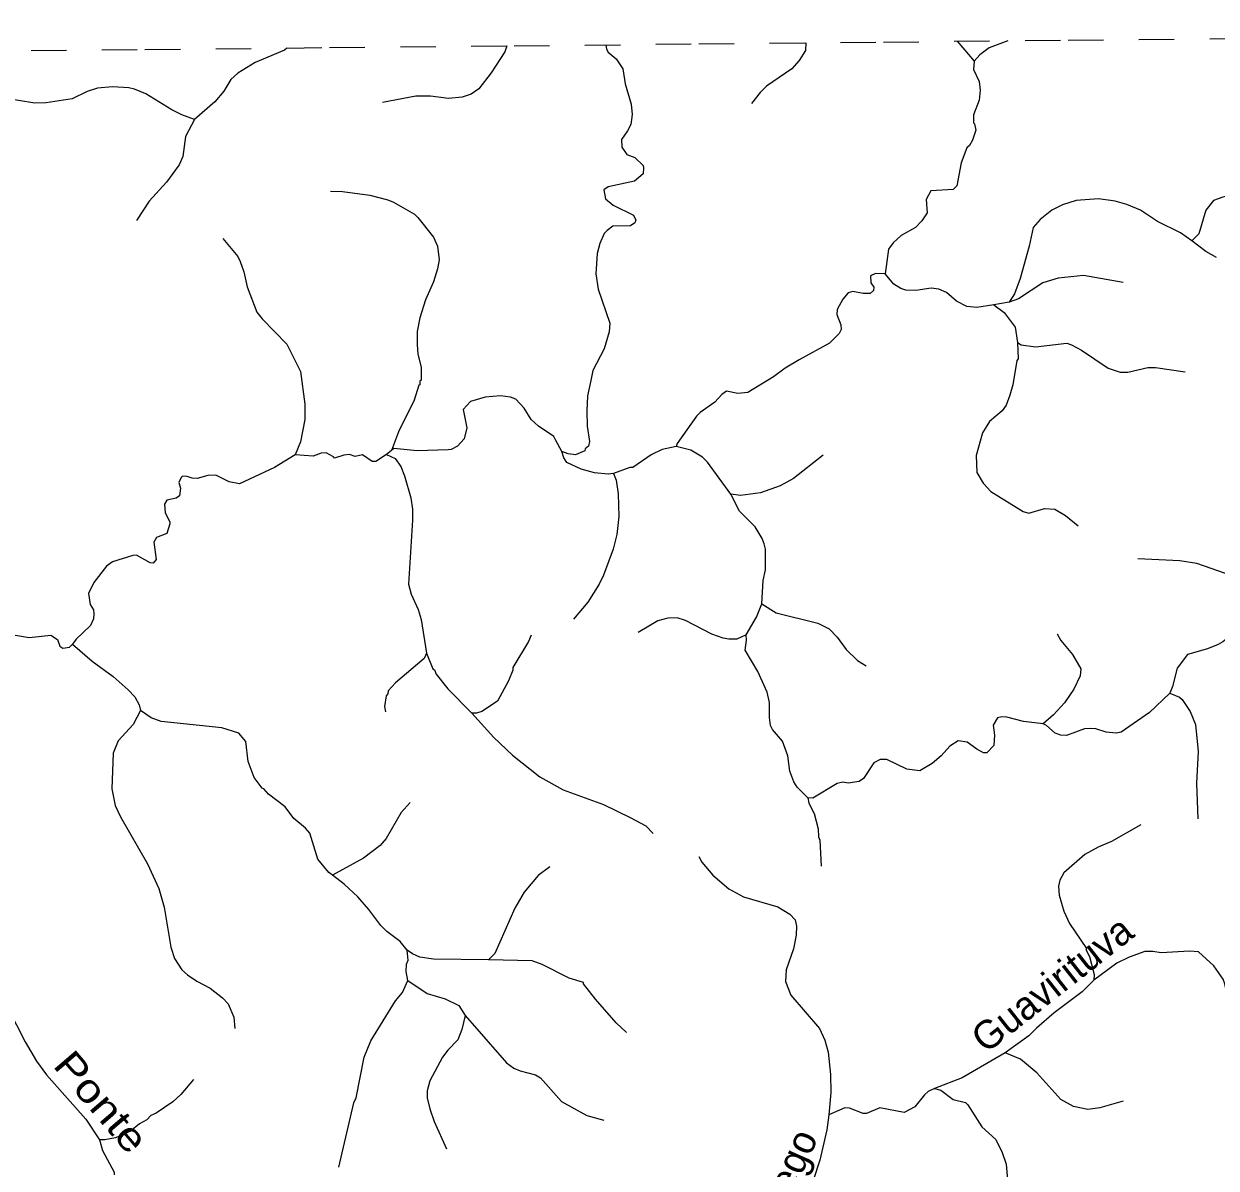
# Model space of a CAD drawing. Extents: x 346.5 to 372.4, y 7400.3 to 7428.2.
# Drawn here: x 348.817 to 352.188, y 7424.867 to 7428.102 of the extents above; entities that cross this region are included whole.
import ezdxf
from ezdxf.enums import TextEntityAlignment as Align

# ---------------------------------------------------------------- set-up
doc = ezdxf.new("R2010")
doc.units = 0
doc.header["$LTSCALE"] = 0.032
doc.linetypes.add('SHORT_DASHED', pattern=[2.7, 1.5, -1.2])
doc.layers.add('53', color=7, linetype='SHORT_DASHED', lineweight=13)
doc.layers.add('7', color=7, linetype='Continuous', lineweight=25)
doc.layers.add('61', color=7, linetype='Continuous')

msp = doc.modelspace()

# ---------------------------------------------------------------- linework, layer by layer
at = {"layer": '53'}
msp.add_lwpolyline([(346.5495, 7428.0029), (347.0715, 7428.0083), (347.5936, 7428.0137), (348.1156, 7428.019), (348.6376, 7428.0243), (349.1596, 7428.0297), (349.6816, 7428.035), (350.2036, 7428.0402), (350.7257, 7428.0455), (351.2477, 7428.0507), (351.7697, 7428.0559), (352.2917, 7428.0611), (352.8137, 7428.0663), (353.3357, 7428.0715), (353.8577, 7428.0766), (354.3798, 7428.0818), (354.9018, 7428.0869), (355.4238, 7428.092), (355.9458, 7428.0971), (356.4678, 7428.1021)], dxfattribs=at)
at = {"layer": '7'}
msp.add_line((351.4558, 7428.0528), (351.5038, 7427.9967), dxfattribs=at)
for points in [[(351.5993, 7428.0542), (351.5466, 7428.0343), (351.5195, 7428.0144), (351.5038, 7427.9967)], [(349.5611, 7428.0338), (349.5543, 7428.0279), (349.4714, 7427.9929), (349.422, 7427.9626), (349.4028, 7427.9451), (349.3821, 7427.9116), (349.3574, 7427.8821), (349.2997, 7427.832)], [(350.1829, 7428.04), (350.1766, 7428.0232), (350.1384, 7427.9634), (350.1033, 7427.9187), (350.0818, 7427.9036), (350.0563, 7427.8948), (350.0181, 7427.8908), (349.9671, 7427.8972), (349.9256, 7427.8972), (349.8308, 7427.8797)], [(350.4626, 7428.0428), (350.4645, 7428.0309), (350.4693, 7428.0224), (350.4914, 7428.0032), (350.5106, 7427.9753), (350.5169, 7427.9323), (350.5337, 7427.8749), (350.5369, 7427.8462), (350.5329, 7427.8175), (350.5241, 7427.7992), (350.5066, 7427.7753), (350.5082, 7427.7538), (350.5217, 7427.7323), (350.5441, 7427.7243), (350.568, 7427.702), (350.5687, 7427.6948), (350.568, 7427.6781), (350.544, 7427.6573), (350.4691, 7427.6414), (350.4572, 7427.6327), (350.4612, 7427.6079), (350.4835, 7427.5896), (350.5409, 7427.5617), (350.5472, 7427.5474), (350.5448, 7427.5394), (350.5321, 7427.5314), (350.4827, 7427.5298), (350.466, 7427.5179), (350.458, 7427.5099), (350.4452, 7427.4812), (350.438, 7427.4525), (350.4341, 7427.3952), (350.4404, 7427.3521), (350.4739, 7427.2557), (350.4723, 7427.231), (350.458, 7427.1832), (350.4261, 7427.1226), (350.4197, 7427.0939), (350.411, 7427.0509), (350.4086, 7427.0078), (350.4102, 7426.9648), (350.4165, 7426.9218), (350.4133, 7426.9082), (350.4038, 7426.9003), (350.403, 7426.8955), (350.3767, 7426.8835), (350.3564, 7426.8861), (350.3379, 7426.8934)], [(351.0284, 7428.0485), (351.027, 7428.0271), (351.0087, 7427.9984), (350.9887, 7427.9745), (350.917, 7427.9259), (350.8987, 7427.9084), (350.8748, 7427.8773)], [(351.5038, 7427.9967), (351.502, 7427.9729), (351.5179, 7427.9395), (351.5211, 7427.9148), (351.5179, 7427.8861), (351.502, 7427.8446), (351.502, 7427.8223), (351.5052, 7427.8199), (351.5083, 7427.8016), (351.4988, 7427.7729), (351.4908, 7427.7578), (351.4836, 7427.7514), (351.4669, 7427.7092), (351.4549, 7427.6446), (351.4446, 7427.6334), (351.3816, 7427.6302), (351.3681, 7427.6056), (351.3713, 7427.5681), (351.3561, 7427.545), (351.3378, 7427.5266), (351.2972, 7427.5035), (351.2748, 7427.4828), (351.2613, 7427.4653), (351.2518, 7427.3956)], [(349.2997, 7427.832), (349.2642, 7427.8446), (349.2355, 7427.859), (349.1622, 7427.9044), (349.1303, 7427.9179), (349.1143, 7427.9211), (349.0681, 7427.9243), (349.0251, 7427.9203), (348.9964, 7427.9108), (348.9534, 7427.8901), (348.88, 7427.8789), (348.8482, 7427.8781), (348.7557, 7427.8932), (348.7246, 7427.8941)], [(349.2997, 7427.832), (349.2745, 7427.7841), (349.2665, 7427.7275), (349.2562, 7427.7036), (349.2203, 7427.655), (349.1717, 7427.6008), (349.1359, 7427.5458)], [(352.6313, 7427.6853), (352.5476, 7427.7068), (352.4838, 7427.7179), (352.4328, 7427.7203), (352.4009, 7427.7147), (352.3579, 7427.6892), (352.2862, 7427.6374), (352.2543, 7427.6231), (352.2065, 7427.6119), (352.1802, 7427.6023), (352.1587, 7427.5753), (352.1395, 7427.5083), (352.1192, 7427.489)], [(349.6841, 7427.6295), (349.7184, 7427.6279), (349.7949, 7427.6175), (349.8459, 7427.6047), (349.8627, 7427.5976), (349.9216, 7427.5641), (349.9312, 7427.5546), (349.975, 7427.4988), (349.9862, 7427.4733), (349.991, 7427.435), (349.987, 7427.4095), (349.975, 7427.3728), (349.9527, 7427.3218), (349.9368, 7427.2708), (349.9288, 7427.2326), (349.9288, 7427.1943), (349.9312, 7427.1688), (349.94, 7427.1306), (349.94, 7427.0947), (349.9368, 7427.0923), (349.9368, 7427.082), (349.9336, 7427.0804), (349.9208, 7427.0381), (349.8762, 7426.9489), (349.8568, 7426.8964)], [(352.1192, 7427.489), (352.0869, 7427.5115), (352.0224, 7427.5434), (351.9738, 7427.5753), (351.9355, 7427.5912), (351.9021, 7427.6008), (351.8558, 7427.6071), (351.7921, 7427.6031), (351.7538, 7427.5904), (351.7235, 7427.5753), (351.6909, 7427.549), (351.6709, 7427.5266), (351.6598, 7427.4733), (351.6343, 7427.3824), (351.6183, 7427.3386), (351.6032, 7427.3157)], [(349.3797, 7427.4956), (349.4219, 7427.4446), (349.4291, 7427.4302), (349.4395, 7427.4015), (349.449, 7427.3585), (349.4761, 7427.2868), (349.4905, 7427.2684), (349.5606, 7427.1967), (349.5989, 7427.1194), (349.6116, 7427.027), (349.6116, 7426.9839), (349.5989, 7426.9202), (349.5845, 7426.8833)], [(352.1894, 7427.4418), (352.1587, 7427.4581), (352.1192, 7427.489)], [(351.2518, 7427.3956), (351.2246, 7427.3959), (351.2111, 7427.3896), (351.2119, 7427.3704), (351.2199, 7427.3577), (351.2191, 7427.3481), (351.2103, 7427.3402), (351.1896, 7427.3402), (351.1609, 7427.3457), (351.1481, 7427.3418), (351.1322, 7427.3234), (351.1162, 7427.2947), (351.1155, 7427.2804), (351.1266, 7427.2517), (351.1282, 7427.2382), (351.1226, 7427.227), (351.0947, 7427.1991), (351.0095, 7427.1521), (350.9696, 7427.129), (350.9362, 7427.1043), (350.8644, 7427.0604), (350.8357, 7427.0572), (350.8039, 7427.0636), (350.7903, 7427.054), (350.7704, 7427.0325), (350.7297, 7427.0038), (350.7186, 7426.9927), (350.6643, 7426.9161), (350.6611, 7426.9073)], [(351.5592, 7427.3074), (351.5115, 7427.3003), (351.4829, 7427.3027), (351.4542, 7427.3178), (351.4255, 7427.3425), (351.4039, 7427.3521), (351.3824, 7427.3553), (351.3394, 7427.3481), (351.3107, 7427.3497), (351.2964, 7427.3537), (351.2772, 7427.3665), (351.2518, 7427.3956)], [(351.9252, 7427.3713), (351.8128, 7427.3904), (351.7411, 7427.3832), (351.698, 7427.3696), (351.6294, 7427.3247), (351.6032, 7427.3157), (351.5592, 7427.3074)], [(351.5592, 7427.3074), (351.5888, 7427.286), (351.6199, 7427.2445), (351.6261, 7427.2013)], [(351.6261, 7427.2013), (351.6278, 7427.1548), (351.6247, 7427.1505), (351.6135, 7427.0812), (351.6048, 7427.0525), (351.5944, 7427.0238), (351.5833, 7427.0078), (351.5474, 7426.9776), (351.5275, 7426.9457), (351.5099, 7426.8819), (351.5115, 7426.8341), (351.5291, 7426.8038), (351.5514, 7426.7799), (351.6422, 7426.7233), (351.6582, 7426.7193), (351.7028, 7426.7321), (351.7315, 7426.7297), (351.7618, 7426.7122), (351.7976, 7426.6827)], [(351.6261, 7427.2013), (351.6364, 7427.1946), (351.6773, 7427.1895), (351.7658, 7427.1991), (351.7793, 7427.1951), (351.8072, 7427.18), (351.8829, 7427.129), (351.9164, 7427.1178), (351.9387, 7427.1178), (351.9945, 7427.1306), (352.0168, 7427.1306), (352.1005, 7427.1186)], [(350.3379, 7426.8934), (350.3201, 7426.9266), (350.3153, 7426.9353), (350.2723, 7426.9648), (350.2516, 7426.9839), (350.2316, 7427.0158), (350.2077, 7427.0413), (350.1934, 7427.0469), (350.1647, 7427.0509), (350.1217, 7427.0469), (350.0802, 7427.0341), (350.0595, 7427.0118), (350.0691, 7426.96), (350.0619, 7426.9289), (350.0436, 7426.9082), (350.0252, 7426.8986), (350.0165, 7426.8978), (349.9288, 7426.8955), (349.8636, 7426.9012), (349.8568, 7426.8964), (349.8427, 7426.8843)], [(350.6611, 7426.9073), (350.6222, 7426.8986), (350.5911, 7426.8835), (350.5393, 7426.8476), (350.5302, 7426.8481), (350.4838, 7426.8311)], [(350.8156, 7426.7727), (350.7504, 7426.8628), (350.7361, 7426.8771), (350.7026, 7426.8974), (350.6611, 7426.9073)], [(349.5845, 7426.8833), (349.5256, 7426.8476), (349.4267, 7426.8022), (349.398, 7426.8078), (349.3598, 7426.8261), (349.3375, 7426.8253), (349.3072, 7426.8166), (349.2929, 7426.8174), (349.2785, 7426.8229), (349.2657, 7426.8237), (349.2618, 7426.8198), (349.2554, 7426.8054), (349.2602, 7426.7895), (349.257, 7426.768), (349.2482, 7426.7616), (349.2211, 7426.7552), (349.2147, 7426.744), (349.2171, 7426.7194), (349.2299, 7426.6946), (349.2299, 7426.6891), (349.2211, 7426.6612), (349.1924, 7426.65), (349.1844, 7426.6373), (349.1916, 7426.5878), (349.1829, 7426.5775), (349.1741, 7426.5783), (349.1359, 7426.5998), (349.1255, 7426.599), (349.0681, 7426.5815), (349.0506, 7426.5687), (349.0147, 7426.5233), (348.9996, 7426.4922), (349.0051, 7426.4611), (349.0139, 7426.446), (349.0155, 7426.434), (349.0139, 7426.4197), (349.0059, 7426.4014), (348.9653, 7426.3631), (348.9543, 7426.3487)], [(349.8427, 7426.8843), (349.8125, 7426.8652), (349.8021, 7426.8652), (349.7742, 7426.8835), (349.7535, 7426.8787), (349.7375, 7426.8843), (349.7216, 7426.8827), (349.6953, 7426.8739), (349.6929, 7426.8779), (349.6722, 7426.8891), (349.6579, 7426.8883), (349.6355, 7426.8803), (349.5845, 7426.8833)], [(349.8427, 7426.8843), (349.8666, 7426.8732), (349.8826, 7426.8508), (349.8937, 7426.8245), (349.9113, 7426.7624), (349.916, 7426.7305), (349.916, 7426.6986), (349.9049, 7426.5185), (349.9121, 7426.4898), (349.932, 7426.4468), (349.9408, 7426.4181), (349.9557, 7426.3226)], [(350.4838, 7426.8311), (350.4691, 7426.8293), (350.4309, 7426.8325), (350.3926, 7426.8429), (350.3524, 7426.8624), (350.3441, 7426.8748), (350.3379, 7426.8934)], [(351.0772, 7426.8827), (350.9927, 7426.8166), (350.9553, 7426.7958), (350.8995, 7426.7759), (350.8437, 7426.7687), (350.8156, 7426.7727)], [(350.4838, 7426.8311), (350.4922, 7426.8118), (350.497, 7426.7735), (350.4994, 7426.7098), (350.4938, 7426.6588), (350.4835, 7426.6173), (350.4564, 7426.544), (350.4436, 7426.5185), (350.4117, 7426.4675), (350.3711, 7426.4189)], [(350.9032, 7426.4621), (350.9074, 7426.5281), (350.9138, 7426.5584), (350.9138, 7426.6173), (350.9106, 7426.6317), (350.9043, 7426.6476), (350.8843, 7426.6803), (350.8405, 7426.7241), (350.8156, 7426.7727)], [(352.2703, 7426.5207), (352.2336, 7426.5416), (352.1332, 7426.5767), (352.0854, 7426.5839), (351.9666, 7426.5902)], [(350.859, 7426.3752), (350.8883, 7426.4246), (350.9032, 7426.4621)], [(350.9032, 7426.4621), (350.9441, 7426.4372), (351.0621, 7426.4077), (351.0939, 7426.3918), (351.117, 7426.3687), (351.1417, 7426.3336), (351.1744, 7426.3025), (351.1983, 7426.2874)], [(350.859, 7426.3752), (350.8325, 7426.3631), (350.8102, 7426.3623), (350.7943, 7426.3655), (350.7624, 7426.3766), (350.6875, 7426.4157), (350.6644, 7426.4229), (350.6381, 7426.4221), (350.6094, 7426.4141), (350.5544, 7426.3814)], [(352.2679, 7426.4043), (352.2065, 7426.3551), (352.1937, 7426.348), (352.1635, 7426.3352), (352.1068, 7426.3193), (352.0774, 7426.2802), (352.065, 7426.2285), (352.0575, 7426.2096)], [(348.5493, 7426.3934), (348.5915, 7426.3822), (348.6154, 7426.3655), (348.641, 7426.3527), (348.6665, 7426.3496), (348.7175, 7426.3527), (348.7557, 7426.3663), (348.794, 7426.3735), (348.8322, 7426.3671), (348.8936, 7426.3735), (348.9119, 7426.3615), (348.9191, 7426.3424), (348.9271, 7426.3376), (348.9461, 7426.3404), (348.9543, 7426.3487)], [(350.2516, 7426.3743), (350.2436, 7426.3559), (350.1998, 7426.2826), (350.1998, 7426.2754), (350.187, 7426.2444), (350.1567, 7426.187), (350.1123, 7426.1581), (350.0965, 7426.1533), (350.0841, 7426.1534)], [(351.0338, 7425.9141), (351.0039, 7425.9447), (350.9943, 7425.9591), (350.9824, 7425.9893), (350.9768, 7426.0324), (350.9616, 7426.0746), (350.9337, 7426.1073), (350.9282, 7426.1184), (350.925, 7426.1408), (350.925, 7426.1838), (350.9186, 7426.2125), (350.8923, 7426.2715), (350.8564, 7426.332), (350.8604, 7426.3594), (350.859, 7426.3752)], [(351.7387, 7426.3775), (351.749, 7426.3591), (351.7817, 7426.3193), (351.8056, 7426.2786), (351.8032, 7426.2587), (351.7857, 7426.2213), (351.7594, 7426.183), (351.7283, 7426.1487), (351.6987, 7426.123)], [(348.9543, 7426.3487), (349.0107, 7426.3001), (349.0697, 7426.2571), (349.1119, 7426.2196), (349.1311, 7426.1997), (349.143, 7426.1766), (349.1471, 7426.1607)], [(349.9557, 7426.3226), (349.9488, 7426.3084), (349.8682, 7426.2396), (349.8467, 7426.2165), (349.8459, 7426.2085), (349.8411, 7426.2021), (349.8372, 7426.1726), (349.8396, 7426.1575)], [(349.9557, 7426.3226), (349.9734, 7426.2786), (349.9782, 7426.2755), (349.983, 7426.2635), (350.0157, 7426.2221), (350.0841, 7426.1534)], [(348.3369, 7426.2025), (348.3883, 7426.1527), (348.4026, 7426.132), (348.4433, 7426.0706), (348.476, 7425.9989), (348.5063, 7425.8969), (348.5246, 7425.8076), (348.5333, 7425.7391), (348.5525, 7425.6945), (348.5724, 7425.661), (348.6226, 7425.5996), (348.7127, 7425.4187), (348.7716, 7425.3207), (348.821, 7425.2243), (348.8529, 7425.1701), (348.8816, 7425.131), (348.9478, 7425.0561), (348.9924, 7425.0059), (349.0314, 7424.9477)], [(352.0575, 7426.2096), (351.9993, 7426.1551), (351.9196, 7426.1001), (351.9052, 7426.0969), (351.8766, 7426.0993), (351.8479, 7426.1089), (351.8319, 7426.1105), (351.816, 7426.1089), (351.765, 7426.0905), (351.749, 7426.0913), (351.7331, 7426.0969), (351.7079, 7426.1186), (351.6987, 7426.123)], [(352.0575, 7426.2096), (352.0846, 7426.1989), (352.0917, 7426.1918), (352.1148, 7426.1583), (352.1292, 7426.1216), (352.1371, 7426.0451), (352.1324, 7425.9559), (352.1364, 7425.8547)], [(349.1471, 7426.1607), (349.1263, 7426.1216), (349.084, 7426.0754), (349.0697, 7426.0404), (349.0657, 7425.9399), (349.0753, 7425.8921), (349.0904, 7425.8602), (349.1669, 7425.728), (349.1988, 7425.6578), (349.2139, 7425.6052), (349.2323, 7425.4921), (349.2434, 7425.4602), (349.2641, 7425.4283), (349.2801, 7425.4139), (349.3064, 7425.3956), (349.3439, 7425.3765), (349.3789, 7425.3486), (349.3949, 7425.3319), (349.4108, 7425.2944), (349.414, 7425.2617)], [(349.6901, 7425.6956), (349.6798, 7425.7032), (349.6483, 7425.7407), (349.626, 7425.814), (349.6132, 7425.8284), (349.5805, 7425.8555), (349.5558, 7425.8889), (349.5088, 7425.9248), (349.4961, 7425.9391), (349.4913, 7425.9415), (349.4682, 7425.9718), (349.4514, 7426.0164), (349.4443, 7426.0738), (349.4251, 7426.0969), (349.3773, 7426.1121), (349.2052, 7426.1296), (349.1773, 7426.14), (349.1471, 7426.1607)], [(350.0841, 7426.1534), (350.1456, 7426.085), (350.199, 7426.0348), (350.2763, 7425.9734), (350.3416, 7425.9367), (350.4564, 7425.8953), (350.5313, 7425.8586), (350.5759, 7425.8347), (350.5967, 7425.8132)], [(351.6987, 7426.123), (351.6438, 7426.1296), (351.596, 7426.1423), (351.5817, 7426.1431), (351.5697, 7426.14), (351.5578, 7426.12), (351.5609, 7426.0914), (351.5593, 7426.0619), (351.5394, 7426.0411), (351.5307, 7426.0411), (351.5115, 7426.0515), (351.4845, 7426.0714), (351.4589, 7426.0754), (351.435, 7426.0603), (351.4103, 7426.0324), (351.3848, 7426.0116), (351.3505, 7425.9909), (351.3139, 7425.9949), (351.2565, 7426.0228), (351.2382, 7426.0228), (351.2206, 7426.0133), (351.1912, 7425.9686), (351.1784, 7425.9606), (351.1481, 7425.9559), (351.1322, 7425.9582), (351.1163, 7425.9543), (351.0475, 7425.9127), (351.0338, 7425.9141)], [(349.9089, 7425.9009), (349.8842, 7425.873), (349.8419, 7425.7989), (349.8244, 7425.779), (349.7774, 7425.7439), (349.6901, 7425.6956)], [(351.0338, 7425.9141), (351.0368, 7425.8992), (351.0517, 7425.8698), (351.0629, 7425.8268), (351.0636, 7425.8036), (351.0676, 7425.7949), (351.0716, 7425.7208)], [(351.9746, 7425.8379), (351.8925, 7425.7909), (351.8542, 7425.775), (351.8168, 7425.7542), (351.7578, 7425.7024), (351.7458, 7425.6817), (351.7427, 7425.6642), (351.7442, 7425.6387), (351.757, 7425.5941), (351.7737, 7425.559), (351.8215, 7425.488), (351.8191, 7425.4849), (351.8304, 7425.4653), (351.8435, 7425.415), (351.8418, 7425.3991)], [(350.7258, 7425.7479), (350.7337, 7425.7327), (350.7648, 7425.6953), (350.8102, 7425.657), (350.8517, 7425.6339), (350.9489, 7425.606), (350.9824, 7425.5853), (350.9975, 7425.5694), (351.0015, 7425.551), (351.0007, 7425.5255), (350.9927, 7425.4873), (350.972, 7425.4283), (350.9704, 7425.3948), (350.9855, 7425.3566), (351.0668, 7425.2625), (351.082, 7425.2291), (351.0907, 7425.1956), (351.0979, 7425.1318), (351.0987, 7425.0808), (351.093, 7425.0176)], [(349.9007, 7425.4837), (349.881, 7425.508), (349.8435, 7425.5359), (349.826, 7425.5534), (349.7925, 7425.5988), (349.7615, 7425.6339), (349.7232, 7425.6705), (349.6901, 7425.6956)], [(350.3042, 7425.7192), (350.2715, 7425.6945), (350.2316, 7425.6474), (350.2053, 7425.602), (350.1488, 7425.4745), (350.1312, 7425.4559)], [(349.9031, 7425.398), (349.8985, 7425.4235), (349.8993, 7425.4442), (349.9034, 7425.4555), (349.9007, 7425.4837)], [(350.1312, 7425.4559), (349.975, 7425.4578), (349.9368, 7425.4633), (349.9161, 7425.4727), (349.9007, 7425.4837)], [(350.5209, 7425.2506), (350.4922, 7425.2785), (350.4333, 7425.3454), (350.3998, 7425.3884), (350.3998, 7425.3924), (350.3592, 7425.4044), (350.2827, 7425.4426), (350.254, 7425.453), (350.1312, 7425.4559)], [(352.2352, 7425.2685), (352.2176, 7425.2976), (352.2176, 7425.3661), (352.2128, 7425.3885), (352.2081, 7425.4012), (352.181, 7425.4394), (352.1379, 7425.4785), (352.1124, 7425.4809), (352.0328, 7425.4761), (352.0088, 7425.4801), (351.9865, 7425.4793), (351.9419, 7425.4633), (351.9068, 7425.4466), (351.8418, 7425.3991)], [(349.7073, 7424.8696), (349.7503, 7425.0521), (349.7567, 7425.0665), (349.779, 7425.1812), (349.7981, 7425.2275), (349.8682, 7425.3398), (349.8874, 7425.3637), (349.9031, 7425.398)], [(349.9031, 7425.398), (349.9575, 7425.3613), (350.0085, 7425.3462), (350.0468, 7425.3271), (350.0651, 7425.2986)], [(351.8418, 7425.3991), (351.8096, 7425.3661), (351.7299, 7425.3063), (351.6797, 7425.2633), (351.6582, 7425.241), (351.5912, 7425.1935)], [(350.0651, 7425.2986), (350.0555, 7425.2593), (350.0444, 7425.2298), (350.0157, 7425.2012), (350.0005, 7425.1812), (349.9647, 7425.1143), (349.9575, 7425.0856), (349.9575, 7425.0665), (349.9647, 7425.0354), (349.9774, 7424.9995), (350.0125, 7424.9222)], [(350.0651, 7425.2986), (350.1814, 7425.1653), (350.2022, 7425.1502), (350.2205, 7425.1422), (350.2635, 7425.131), (350.2779, 7425.1223), (350.3368, 7425.0553), (350.4086, 7425.0163), (350.4572, 7425.0027)], [(351.5912, 7425.1935), (351.4701, 7425.123), (351.392, 7425.0928)], [(351.9252, 7425.0569), (351.859, 7425.0378), (351.8255, 7425.033), (351.7849, 7425.0418), (351.749, 7425.0609), (351.6813, 7425.1366), (351.6351, 7425.1749), (351.5912, 7425.1935)], [(349.2968, 7425.1183), (349.261, 7425.0752), (349.2387, 7425.0545), (349.1908, 7425.0226), (349.1765, 7425.0163), (349.1653, 7425.0035), (349.1446, 7424.9923), (349.1191, 7424.9716), (349.0761, 7424.9533), (349.0462, 7424.9472), (349.0314, 7424.9477)], [(351.392, 7425.0928), (351.3737, 7425.084), (351.3633, 7425.0745), (351.3362, 7425.0402), (351.3059, 7425.025), (351.2374, 7425.0378), (351.1999, 7425.0218), (351.1896, 7425.0218), (351.1513, 7425.037), (351.1386, 7425.0378), (351.093, 7425.0176)], [(351.392, 7425.0928), (351.4094, 7425.0878), (351.4446, 7425.0609), (351.4789, 7425.0529), (351.486, 7425.0466), (351.5259, 7424.9844), (351.5649, 7424.9485), (351.5833, 7424.9119), (351.5944, 7424.8784), (351.5984, 7424.8338), (351.5939, 7424.799)], [(351.093, 7425.0176), (351.0876, 7424.9756), (351.0676, 7424.8896), (351.0302, 7424.7748), (351.0226, 7424.7398)], [(349.0314, 7424.9477), (349.0394, 7424.9167), (349.0725, 7424.8555), (349.0725, 7424.8479)]]:
    msp.add_lwpolyline(points, dxfattribs=at)

# ---------------------------------------------------------------- texts
at = {"layer": '61'}
for s, rotation, p in [('Guavirituva', 38.245, (351.749, 7425.3567)), ('Córrego', 66.087, (350.9858, 7424.7768))]:
    msp.add_text(s, height=0.08, rotation=rotation, dxfattribs=at).set_placement(p, align=Align.CENTER)
at = {"layer": '61', "width": 1.2}
msp.add_text('Ponte', height=0.08, rotation=310.544, dxfattribs=at).set_placement((349.0057, 7425.0288), align=Align.CENTER)

doc.saveas('drawing.dxf')
